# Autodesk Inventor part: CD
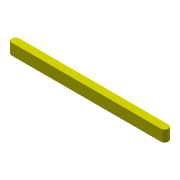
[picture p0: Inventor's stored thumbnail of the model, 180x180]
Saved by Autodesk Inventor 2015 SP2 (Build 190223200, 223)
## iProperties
Created: 2019-08
Part Number: CD
Material: 一般
Document SubType Name: Modeling
Designer: Kuan_Lun Hsu
Density: 1 g/cm^3
Appearance: 平滑 - 黃色
Mass: 0.43927 g
Surface Area: 6.30686 cm^2
Volume: 0.43927 cm^3
Author: Kuan_Lun Hsu
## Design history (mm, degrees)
sketch "草圖1"
  geometry: L1 (0, 0)-(40, 0); L2 (0, -2.5)-(40, -2.5); L3 (40, 2.5)-(0, 2.5); A1 r 2.5 centre (0, 0) between (0, 2.5) and (0, -2.5); A2 r 2.5 centre (40, 0) between (40, -2.5) and (40, 2.5); 1 further point
  constraints: 8 end point, 4 point on circle, 4 tangent, 2 centre point, 1 horizontal, 1 midpoint, 1 parallel
  dimensions: "d0" = 40 distance of L1.start L1.end (= CD_); "d1" = 5 distance between parallel lines of L2 L3 (= w_)
extrude "擠出1" new body sketch "草圖1" distance "d2" = 2 (= t_); taper "d3" = 0 deg
node "實體1"
other parameters: "CD_" = 40 [user parameter; used in 1 equation term], "w_" = 5 [user parameter; used in 1 equation term], "t_" = 2 [user parameter; used in 1 equation term]
